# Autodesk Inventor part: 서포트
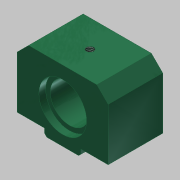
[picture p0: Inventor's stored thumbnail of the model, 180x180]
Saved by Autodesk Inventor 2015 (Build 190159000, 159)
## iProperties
Created: 2019-04
Part Number: 서포트
Material: 알루미늄 6061
Document SubType Name: Modeling
Designer: mduedu
Density: 1 g/cm^3
Appearance: 매끄러움 - 짙은 바다 녹색
Author: mduedu
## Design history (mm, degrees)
sketch "스케치1"
  geometry: L1 (3, 20)-(31, 20); L2 (31, 20)-(31, -20); L3 (31, -20)-(3, -20); L4 (0, -8)-(0, 8); L5 (0, 8)-(3, 8); L6 (3, 8)-(3, 20); L7 (0, 0)-(31, 0); L8 (0, -8)-(3, -8); L9 (3, -8)-(3, -20); 1 further point
  constraints: 18 end point, 3 symmetric about line, 2 horizontal, 2 midpoint, 2 parallel, 2 perpendicular, 1 coincident
  dimensions: "d3" = 31 distance between parallel lines of L4 L2; "d5" = 16 distance of L4.start L4.end; "d6" = 40 distance between parallel lines of L3 L1; "d7" = 3 distance between parallel lines of L4 L9
extrude "돌출1" new body sketch "스케치1" distance "d8" = 24; taper "d9" = 0 deg
chamfer "모따기1" distance "d10" = 5; stored, may be unused: second distance "d11" = 2, angle "d12" = 45 deg
chamfer "모따기2" distance "d13" = 1; stored, may be unused: second distance "d14" = 2, angle "d15" = 45 deg
sketch "스케치2"
  geometry: L1 (7, 0)-(-7, 0) reference; L2 (20, 3)-(8, 3) reference; 3 further points
  constraints: 1 midpoint, 1 vertical alignment
  dimensions: "d24" = 12 distance from line of point (0, 15) L2
hole "구멍1" sketch "스케치2" at (0, 15) diameter "d17" = 17; stored, may be unused: countersink angle "d21" = 90 deg, drill point angle "d23" = 118 deg; dims "d18" = 6, "d19" = 21, "d20" = 3, "d22" = 8
sketch "스케치3"
  geometry: L1 (0, 30)-(0, 0) reference; 3 further points
  constraints: 1 horizontal alignment, 1 midpoint
  dimensions: "d25" = 12 distance from line of point (12, 15) L1
hole "구멍2" sketch "스케치3" at (12, 15) diameter "d26" = 3.242; stored, may be unused: countersink angle "d30" = 90 deg, drill point angle "d32" = 118 deg; dims "d27" = 6, "d28" = 21, "d29" = 3, "d31" = 8
sketch "스케치4"
  geometry: L1 (0, -8)-(24, -8); L2 (24, 0.5)-(24, -16.5) reference; L3 (0, -28)-(0, -23) reference; 4 further points
  constraints: 2 end point, 2 symmetric about line, 1 horizontal, 1 horizontal alignment, 1 midpoint
  dimensions: "d33" = 6 distance from line of point (6, -22) L3; "d34" = 12 distance of point (18, -22) point (6, -22); "d35" = 28 distance of point (6, 6) point (6, -22); "d36" = 14 distance from line of point (6, -22) L1 (derived)
hole "구멍3" sketch "스케치4" at (6, -22), (18, -22), (18, 6), (6, 6) diameter "d37" = 3.242; stored, may be unused: countersink angle "d41" = 90 deg, drill point angle "d43" = 118 deg; dims "d38" = 9, "d39" = 21, "d40" = 3, "d42" = 11
node "솔리드1"
